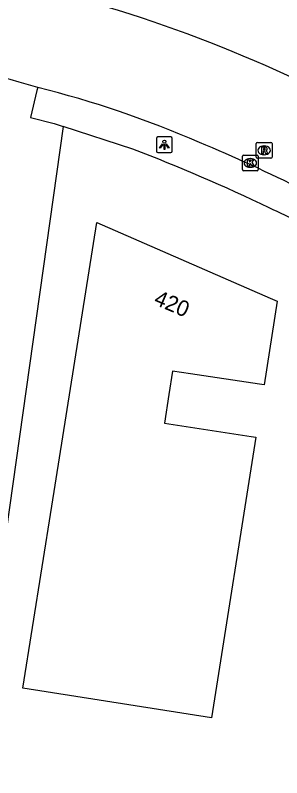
# Model space of a CAD drawing. Extents: x 154324 to 155743, y 382939 to 384183.
# Drawn here: x 155330.84 to 155347.79, y 383421.74 to 383470.22 of the extents above; entities that cross this region are included whole.
import ezdxf

# ---------------------------------------------------------------- set-up
doc = ezdxf.new("R2010")
doc.units = 0
for name, color, linetype in [('IMGEO_Groenvoorziening', 7, 'Continuous'), ('IMGEO_Kolk', 7, 'Continuous'), ('IMGEO_Lichtpunt', 7, 'Continuous'), ('IMGEO_Pand', 7, 'Continuous'), ('IMGEO_Pand_nummerreeks', 7, 'Continuous'), ('IMGEO_Rijbaan_lokaal_open', 7, 'Continuous'), ('IMGEO_Rioolput', 7, 'Continuous'), ('IMGEO_Voetpad_open', 7, 'Continuous')]:
    doc.layers.add(name, color=color, linetype=linetype)

msp = doc.modelspace()

# ---------------------------------------------------------------- linework, layer by layer
at = {"layer": 'IMGEO_Groenvoorziening'}
msp.add_lwpolyline([(155333.894, 383463.145), (155328.096, 383422.22), (155326.654, 383413.134), (155323.037, 383390.342)], dxfattribs=at)
at = {"layer": 'IMGEO_Kolk'}
for p, q in [((155345.293, 383460.408), (155345.293, 383461.26)), ((155345.368, 383461.334), (155346.22, 383461.334)), ((155346.294, 383461.26), (155346.294, 383460.408)), ((155345.781, 383461.114), (155345.806, 383461.114)), ((155346.22, 383460.334), (155345.368, 383460.334)), ((155345.804, 383460.554), (155345.779, 383460.554))]:
    msp.add_line(p, q, dxfattribs=at)
for points in [[(155345.293, 383460.408), (155345.293, 383461.26)], [(155345.368, 383461.334), (155346.22, 383461.334)], [(155346.294, 383461.26), (155346.294, 383460.408)], [(155345.614, 383461.034), (155345.737, 383461.034), (155345.737, 383460.883), (155345.867, 383461.034), (155346.031, 383461.034), (155345.885, 383460.883), (155346.038, 383460.634), (155345.886, 383460.634), (155345.801, 383460.798), (155345.737, 383460.731), (155345.737, 383460.634), (155345.614, 383460.634), (155345.614, 383461.034)], [(155346.22, 383460.334), (155345.368, 383460.334)]]:
    msp.add_lwpolyline(points, dxfattribs=at)
for centre, start, end in [((155345.37, 383461.258), 91.552, 178.448), ((155345.37, 383461.258), 91.552, 178.448), ((155346.218, 383461.258), 1.552, 88.448), ((155346.218, 383461.258), 1.552, 88.448), ((155345.37, 383460.41), 181.552, 268.448), ((155345.37, 383460.41), 181.552, 268.448), ((155346.218, 383460.41), 271.552, 358.448), ((155346.218, 383460.41), 271.552, 358.448)]:
    msp.add_arc(centre, 0.0765, start, end, dxfattribs=at)
for centre, major_axis, ratio, start_param, end_param in [((155345.78, 383460.834), (-0.387, 0.002), 0.722429, 4.712389, 7.853982), ((155345.805, 383460.834), (-0.39, 0.002), 0.717154, 1.570796, 4.712389)]:
    msp.add_ellipse(centre, major_axis=major_axis, ratio=ratio, start_param=start_param, end_param=end_param, dxfattribs=at)
at = {"layer": 'IMGEO_Lichtpunt'}
for p, q in [((155339.826, 383462.393), (155339.826, 383461.586)), ((155339.826, 383462.393), (155339.826, 383461.586)), ((155340.728, 383462.488), (155339.92, 383462.488)), ((155340.728, 383462.488), (155339.92, 383462.488)), ((155340.822, 383461.586), (155340.822, 383462.393)), ((155340.822, 383461.586), (155340.822, 383462.393)), ((155339.92, 383461.492), (155340.728, 383461.492)), ((155339.92, 383461.492), (155340.728, 383461.492))]:
    msp.add_line(p, q, dxfattribs=at)
for points in [[(155340.2, 383462.057), (155340.239, 383462.029), (155340.051, 383461.767), (155340.013, 383461.794), (155340.2, 383462.057)], [(155340.302, 383462.009), (155340.349, 383462.009), (155340.349, 383461.687), (155340.302, 383461.687), (155340.302, 383462.009)], [(155340.412, 383462.029), (155340.45, 383462.056), (155340.637, 383461.794), (155340.598, 383461.766), (155340.412, 383462.029)]]:
    msp.add_lwpolyline(points, dxfattribs=at)
msp.add_circle((155340.325, 383462.191), 0.0994, dxfattribs=at)
for centre, start, end in [((155339.92, 383462.393), 90, 180), ((155339.92, 383462.393), 90, 180), ((155340.728, 383462.393), 0, 90), ((155340.728, 383462.393), 0, 90), ((155339.92, 383461.586), 180, 270), ((155339.92, 383461.586), 180, 270), ((155340.728, 383461.586), 270, 0), ((155340.728, 383461.586), 270, 360)]:
    msp.add_arc(centre, 0.0946, start, end, dxfattribs=at)
at = {"layer": 'IMGEO_Pand'}
msp.add_lwpolyline([(155343.315, 383425.544), (155331.323, 383427.445), (155333.164, 383439.018), (155336.033, 383457.049), (155347.048, 383452.243), (155347.501, 383452.045), (155346.667, 383446.721), (155346.37, 383446.766), (155341.993, 383447.428), (155340.844, 383447.602), (155340.619, 383446.119), (155340.34, 383444.275), (155345.852, 383443.441), (155346.148, 383443.396), (155343.315, 383425.544)], dxfattribs=at)
at = {"layer": 'IMGEO_Rijbaan_lokaal_open'}
for centre, radius, start, end in [((155312.033, 383388.632), 85.735, 58.41362, 74.83277), ((155304.104, 383368.576), 101.064, 73.81877, 84.84587), ((155315.957, 383400.762), 66.893, 66.57551, 75.8872), ((155302.55, 383366.417), 103.746, 63.30392, 67.32185)]:
    msp.add_arc(centre, radius, start, end, dxfattribs=at)
at = {"layer": 'IMGEO_Rioolput'}
for p, q in [((155346.247, 383462.133), (155347.099, 383462.133)), ((155346.172, 383461.207), (155346.172, 383462.059)), ((155346.66, 383461.913), (155346.685, 383461.913)), ((155347.173, 383462.059), (155347.173, 383461.207)), ((155346.683, 383461.353), (155346.658, 383461.353)), ((155347.099, 383461.133), (155346.247, 383461.133))]:
    msp.add_line(p, q, dxfattribs=at)
for points in [[(155346.247, 383462.133), (155347.099, 383462.133)], [(155346.172, 383461.207), (155346.172, 383462.059)], [(155346.761, 383461.831), (155346.509, 383461.833), (155346.509, 383461.433)], [(155346.687, 383461.752), (155346.633, 383461.752), (155346.633, 383461.671)], [(155346.633, 383461.671), (155346.685, 383461.671)], [(155347.173, 383462.059), (155347.173, 383461.207)], [(155346.509, 383461.433), (155346.633, 383461.433), (155346.633, 383461.595), (155346.644, 383461.595)], [(155346.691, 383461.566), (155346.762, 383461.433), (155346.902, 383461.433), (155346.837, 383461.559)], [(155347.099, 383461.133), (155346.247, 383461.133)]]:
    msp.add_lwpolyline(points, dxfattribs=at)
for centre, radius, start, end in [((155346.249, 383462.057), 0.0765, 91.552, 178.448), ((155346.249, 383462.057), 0.0765, 91.552, 178.448), ((155347.097, 383462.057), 0.0765, 1.552, 88.448), ((155347.097, 383462.057), 0.0765, 1.552, 88.448), ((155346.669, 383461.86), 0.19, 274.7715, 282.9687), ((155346.693, 383461.656), 0.0964, 77.0061, 93.1865), ((155346.707, 383461.713), 0.0378, 276.6634, 79.6772), ((155346.76, 383461.721), 0.109, 350.3612, 89.416), ((155346.758, 383461.721), 0.112, 277.5842, 350.9817), ((155346.249, 383461.209), 0.0765, 181.552, 268.448), ((155346.249, 383461.209), 0.0765, 181.552, 268.448), ((155346.643, 383461.542), 0.0533, 26.0293, 88.6989), ((155346.742, 383461.506), 0.108, 29.5134, 73.7905), ((155347.097, 383461.209), 0.0765, 271.552, 358.448), ((155347.097, 383461.209), 0.0765, 271.552, 358.448)]:
    msp.add_arc(centre, radius, start, end, dxfattribs=at)
for centre, major_axis, ratio, start_param, end_param in [((155346.659, 383461.633), (-0.387, 0.002), 0.722429, 4.712389, 7.853982), ((155346.684, 383461.633), (-0.39, 0.002), 0.717154, 1.570796, 4.712389)]:
    msp.add_ellipse(centre, major_axis=major_axis, ratio=ratio, start_param=start_param, end_param=end_param, dxfattribs=at)
at = {"layer": 'IMGEO_Voetpad_open'}
for points in [[(155332.268, 383465.636), (155332.222, 383465.445), (155331.811, 383463.731), (155333.316, 383463.332), (155333.894, 383463.145)], [(155338.312, 383461.713), (155333.894, 383463.145)]]:
    msp.add_lwpolyline(points, dxfattribs=at)
for centre, radius, start, end in [((155299.548, 383359.815), 109.022, 64.20617, 69.17205), ((155325.371, 383410.082), 52.545, 60.8513, 65.7078)]:
    msp.add_arc(centre, radius, start, end, dxfattribs=at)

# ---------------------------------------------------------------- texts
at = {"layer": 'IMGEO_Pand_nummerreeks'}
msp.add_text('420', height=1, rotation=336.9232, dxfattribs=at).set_placement((155339.593, 383451.868))

doc.saveas('drawing.dxf')
